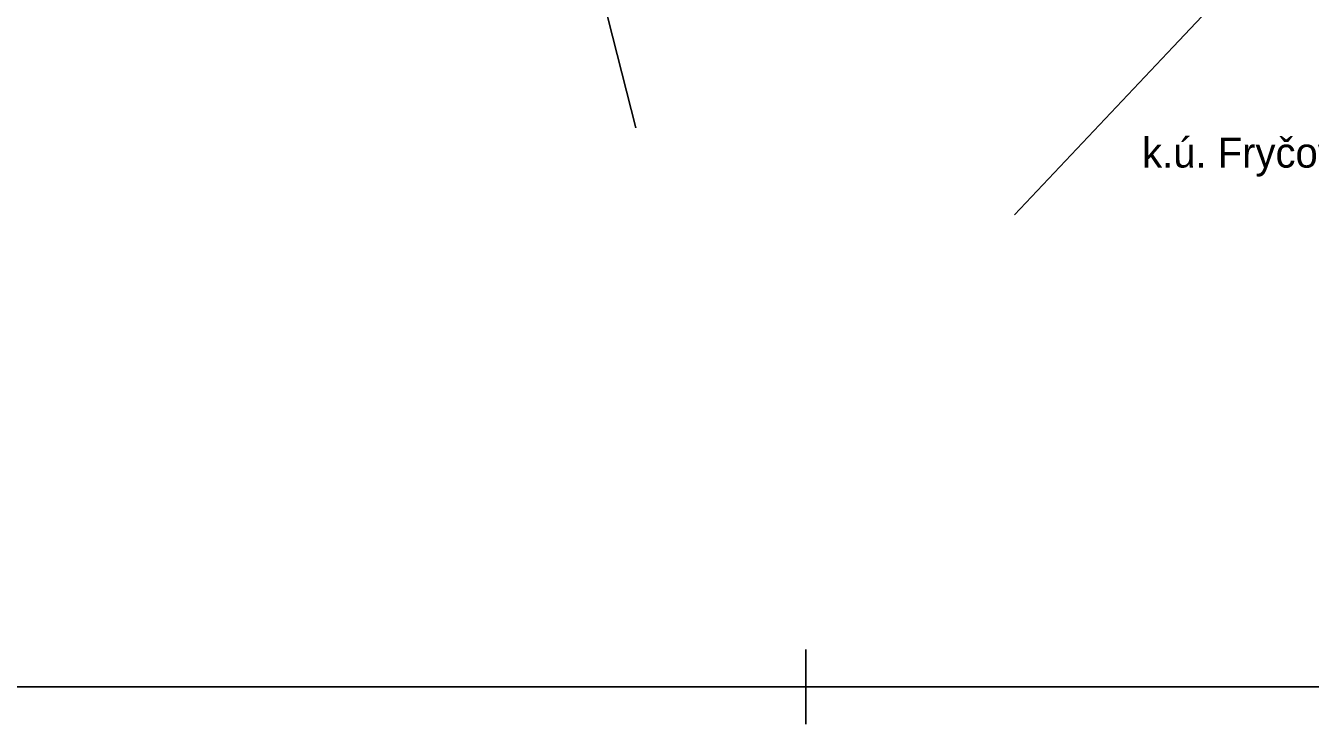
# Model space of a CAD drawing. Extents: x -478464 to -472469, y -1118040 to -1113785.
# Drawn here: x -477215 to -476357, y -1118040 to -1117573 of the extents above; entities that cross this region are included whole.
import ezdxf

# ---------------------------------------------------------------- set-up
doc = ezdxf.new("R2010")
doc.units = 0
for name, color, linetype in [('el vedeni_VVN', 7, 'Continuous'), ('Implicitní', 7, 'Continuous'), ('okolní k_ú_', 7, 'Continuous'), ('plyn_vtl', 7, 'Continuous'), ('Z_razitko', 7, 'Continuous')]:
    doc.layers.add(name, color=color, linetype=linetype)

msp = doc.modelspace()

# ---------------------------------------------------------------- linework, layer by layer
at = {"layer": 'el vedeni_VVN'}
msp.add_line((-476448.364, -1117586.796), (-476554.56, -1117699.163), dxfattribs=at)
msp.add_lwpolyline([(-476448.364, -1117586.796), (-476448.364, -1117586.796), (-476317.643, -1117448.402)], dxfattribs=at)
msp.add_lwpolyline([(-476448.364, -1117586.796), (-476448.364, -1117586.796), (-476317.643, -1117448.402)], dxfattribs=at)
msp.add_lwpolyline([(-476448.364, -1117586.796), (-476448.364, -1117586.796), (-476317.643, -1117448.402)], dxfattribs=at)
at = {"layer": 'Implicitní'}
for p, q in [((-476693.995, -1117989.675), (-476693.995, -1118039.675)), ((-476693.995, -1117989.675), (-476693.995, -1118039.675)), ((-476693.995, -1117989.675), (-476693.995, -1118039.675)), ((-476693.995, -1117989.675), (-476693.995, -1118039.675)), ((-476693.995, -1117989.675), (-476693.995, -1118039.675)), ((-476693.995, -1117989.675), (-476693.995, -1118039.675)), ((-476693.995, -1117989.675), (-476693.995, -1118039.675)), ((-476693.995, -1117989.675), (-476693.995, -1118039.675)), ((-476693.995, -1117989.675), (-476693.995, -1118039.675)), ((-476693.995, -1117989.675), (-476693.995, -1118039.675)), ((-476693.995, -1117989.675), (-476693.995, -1118039.675)), ((-476693.995, -1117989.675), (-476693.995, -1118039.675)), ((-476693.995, -1117989.675), (-476693.995, -1118039.675)), ((-476693.995, -1117989.675), (-476693.995, -1118039.675)), ((-476693.995, -1117989.675), (-476693.995, -1118039.675)), ((-476693.995, -1117989.675), (-476693.995, -1118039.675)), ((-476693.995, -1117989.675), (-476693.995, -1118039.675)), ((-476668.995, -1118014.675), (-476718.995, -1118014.675)), ((-476668.995, -1118014.675), (-476718.995, -1118014.675)), ((-476668.995, -1118014.675), (-476718.995, -1118014.675)), ((-476668.995, -1118014.675), (-476718.995, -1118014.675)), ((-476668.995, -1118014.675), (-476718.995, -1118014.675)), ((-476668.995, -1118014.675), (-476718.995, -1118014.675)), ((-476668.995, -1118014.675), (-476718.995, -1118014.675)), ((-476668.995, -1118014.675), (-476718.995, -1118014.675)), ((-476668.995, -1118014.675), (-476718.995, -1118014.675)), ((-476668.995, -1118014.675), (-476718.995, -1118014.675)), ((-476668.995, -1118014.675), (-476718.995, -1118014.675)), ((-476668.995, -1118014.675), (-476718.995, -1118014.675)), ((-476668.995, -1118014.675), (-476718.995, -1118014.675)), ((-476668.995, -1118014.675), (-476718.995, -1118014.675)), ((-476668.995, -1118014.675), (-476718.995, -1118014.675)), ((-476668.995, -1118014.675), (-476718.995, -1118014.675)), ((-476668.995, -1118014.675), (-476718.995, -1118014.675))]:
    msp.add_line(p, q, dxfattribs=at)
at = {"layer": 'plyn_vtl'}
msp.add_lwpolyline([(-476807.539, -1117641.044), (-476845.2, -1117492.76), (-476870.94, -1117395.8), (-476871.43, -1117390.49), (-476872.65, -1117388.81), (-476881.04, -1117350.81), (-476885.089, -1117338.623), (-476885.25, -1117338.15), (-476884.46, -1117337.68), (-476892.45, -1117313.5), (-476884.4, -1117251.02), (-476853.71, -1117059.16), (-476824.27, -1116852.24), (-476807.41, -1116714.75), (-476840.86, -1116589.24)], dxfattribs=at)
at = {"layer": 'Z_razitko'}
msp.add_lwpolyline([(-478438.995, -1118014.675), (-472493.995, -1118014.675), (-472493.995, -1113809.675), (-478438.995, -1113809.675)], close=True, dxfattribs=at)

# ---------------------------------------------------------------- texts
at = {"layer": 'okolní k_ú_'}
msp.add_text('k.ú. Fryčovice', height=20, rotation=359.961886, dxfattribs=at).set_placement((-476469.21, -1117667.528))

doc.saveas('drawing.dxf')
